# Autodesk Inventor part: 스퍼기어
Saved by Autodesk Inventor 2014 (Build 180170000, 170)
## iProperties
Created: 2026-03
Part Number: 스퍼기어
Material: 강철, 합금
Document SubType Name: Modeling
Designer: dg
Density: 7.85 g/cm^3
Appearance: 반연마
Mass: 181.376 g
Surface Area: 82.8661 cm^2
Volume: 23.1052 cm^3
Author: jhkim
Creation Date: 2025-06-27
Sending System: Autodesk Inventor 2026
Preprocessor: ST-DEVELOPER v20.1
Author: dg
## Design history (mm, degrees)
node "스퍼기어1"
node "솔리드1"
node "기준1"
